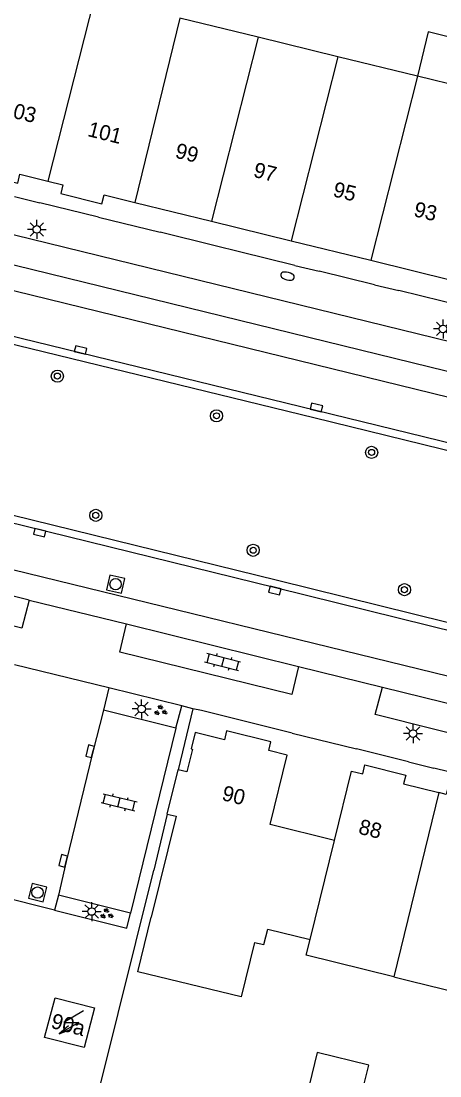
# Model space of a CAD drawing. Extents: x 125000 to 129004, y 397500 to 399008.
# Drawn here: x 126409.3 to 126436.9, y 398309.3 to 398378.8 of the extents above; entities that cross this region are included whole.
import ezdxf

# ---------------------------------------------------------------- set-up
doc = ezdxf.new("R2010")
doc.units = 0
for name, color, linetype in [('gg-afsc-hekwerk', 7, 'Continuous'), ('gg-afsc-muur', 7, 'Continuous'), ('gg-anno-huisnummerreeks BGT', 7, 'Continuous'), ('gg-bbg-gedigitaliseerde bebouwing', 7, 'Continuous'), ('gg-bbg-hoofdgebouw', 7, 'Continuous'), ('gg-bbg-luifel en loopbrug', 7, 'Continuous'), ('gg-bbg-tussenscheiding', 7, 'Continuous'), ('gg-knt-verharding', 7, 'Continuous'), ('gg-knt-verharding nz', 7, 'Continuous'), ('gt-grn-weggrens', 7, 'Continuous'), ('gt-symb-boom', 7, 'Continuous'), ('gt-symb-brandkraan', 7, 'Continuous'), ('gt-symb-groenvak', 7, 'Continuous'), ('gt-symb-klinker verharding', 7, 'Continuous'), ('gt-symb-kolk', 7, 'Continuous'), ('gt-symb-lichtmast', 7, 'Continuous'), ('gt-symb-rioolschacht', 7, 'Continuous'), ('gt-symb-trafo symbool', 7, 'Continuous')]:
    doc.layers.add(name, color=color, linetype=linetype)

# ---------------------------------------------------------------- blocks, each defined once
blk = doc.blocks.new('gt0-LMAST')
at = {"layer": 'gt-symb-lichtmast'}
for p, q in [((-0.182, 0.173), (-0.447, 0.438)), ((-0.005, 0.246), (-0.005, 0.621)), ((0.172, 0.173), (0.437, 0.438)), ((-0.255, -0.004), (-0.63, -0.004)), ((-0.182, -0.181), (-0.447, -0.446)), ((-0.005, -0.254), (-0.005, -0.629)), ((0.437, -0.446), (0.172, -0.181)), ((0.245, -0.004), (0.62, -0.004))]:
    blk.add_line(p, q, dxfattribs=at)
blk.add_circle((-0.005, -0.004), 0.25, dxfattribs=at)
blk = doc.blocks.new('gt0-KOLK')
at = {"layer": 'gt-symb-kolk'}
blk.add_lwpolyline([(0, 0), (0.375, 0), (0.375, 0.4), (-0.375, 0.4), (-0.375, 0), (0, 0)], dxfattribs=at)
blk = doc.blocks.new('gt0-GRVAK')
at = {"layer": 'gt-symb-groenvak'}
for p, q in [((-0.11, 0.189), (-0.228, 0.24)), ((-0.182, 0.153), (0.088, 0.153)), ((-0.091, 0.211), (-0.156, 0.322)), ((-0.047, 0.214), (-0.047, 0.393)), ((-0.004, 0.211), (0.061, 0.322)), ((0.015, 0.189), (0.133, 0.24)), ((0.262, -0.052), (0.197, 0.059)), ((0.305, -0.049), (0.305, 0.13)), ((0.349, -0.052), (0.414, 0.059)), ((-0.245, -0.228), (-0.363, -0.177)), ((-0.318, -0.264), (-0.047, -0.264)), ((-0.226, -0.206), (-0.291, -0.095)), ((-0.183, -0.203), (-0.183, -0.024)), ((-0.139, -0.206), (-0.074, -0.095)), ((-0.12, -0.228), (-0.002, -0.177)), ((0.243, -0.074), (0.125, -0.023)), ((0.17, -0.11), (0.441, -0.11)), ((0.368, -0.074), (0.486, -0.023))]:
    blk.add_line(p, q, dxfattribs=at)
blk = doc.blocks.new('gt0-KL1')
at = {"layer": 'gt-symb-klinker verharding'}
for p, q in [((-1.15, 0.3), (1.15, 0.3)), ((-1, -0.3), (-1, 0.3)), ((-0.5, 0.3), (-0.5, 0.45)), ((0, -0.3), (0, 0.3)), ((0.5, 0.3), (0.5, 0.45)), ((1, -0.3), (1, 0.3)), ((-1.15, -0.3), (1.15, -0.3)), ((-0.5, -0.45), (-0.5, -0.3)), ((0.5, -0.45), (0.5, -0.3))]:
    blk.add_line(p, q, dxfattribs=at)
blk = doc.blocks.new('gt0-RS')
at = {"layer": 'gt-symb-rioolschacht'}
blk.add_lwpolyline([(-0.5, -0.5), (0.5, -0.5), (0.5, 0.5), (-0.5, 0.5)], close=True, dxfattribs=at)
blk.add_circle((0, 0), 0.375, dxfattribs=at)
blk = doc.blocks.new('gt0-HSP')
at = {"layer": 'gt-symb-trafo symbool'}
for points in [[(0.771, 0.746), (-0.529, -0.004), (0.471, -0.004), (-0.829, -0.754)], [(-0.217, -0.24), (-0.829, -0.754), (-0.077, -0.48)]]:
    blk.add_lwpolyline(points, dxfattribs=at)
blk = doc.blocks.new('gt0-BR')
at = {"layer": 'gt-symb-brandkraan'}
for centre, radius, start, end in [((-0.244, 0), 0.206, 107.56694, 252.43307), ((0.599, -2.664), 3, 106.89205, 107.56694), ((0, -0.691), 0.938, 73.10799, 106.89205), ((-0.599, -2.664), 3, 72.43309, 73.10799), ((0.244, 0), 0.206, 287.56695, 72.43309), ((0.599, 2.664), 3, 252.43307, 253.10797), ((0, 0.691), 0.938, 253.10797, 286.89206), ((-0.599, 2.664), 3, 286.89206, 287.56695)]:
    blk.add_arc(centre, radius, start, end, dxfattribs=at)
blk = doc.blocks.new('gt0-BOOM')
at = {"layer": 'gt-symb-boom'}
for radius in [0.4, 0.2]:
    blk.add_circle((0, 0), radius, dxfattribs=at)

msp = doc.modelspace()

# ---------------------------------------------------------------- linework, layer by layer
at = {"layer": 'gg-afsc-hekwerk'}
msp.add_line((126414.543, 398308.615), (126418.065, 398322.828), dxfattribs=at)
at = {"layer": 'gg-afsc-muur'}
for p, q in [((126414.429, 398365.859), (126410.562, 398366.806)), ((126422.12, 398363.973), (126418.482, 398364.873)), ((126427.37, 398362.69), (126423.724, 398363.588)), ((126432.61, 398361.413), (126428.972, 398362.305)), ((126443.124, 398358.85), (126434.215, 398361.037)), ((126427.199, 398331.86), (126421.219, 398333.347)), ((126434.865, 398329.972), (126431.431, 398330.821)), ((126440.386, 398328.611), (126436.524, 398329.564))]:
    msp.add_line(p, q, dxfattribs=at)
at = {"layer": 'gg-bbg-gedigitaliseerde bebouwing'}
msp.add_lwpolyline([(126424.7, 398318.075), (126423.823, 398314.48), (126417.022, 398316.139), (126417.899, 398319.734)], dxfattribs=at)
at = {"layer": 'gg-bbg-hoofdgebouw'}
for p, q in [((126424.952, 398377.721), (126419.787, 398378.984)), ((126430.203, 398376.437), (126424.952, 398377.721)), ((126435.443, 398375.156), (126430.203, 398376.437)), ((126440.76, 398373.855), (126435.443, 398375.156)), ((126416.811, 398366.835), (126421.875, 398365.593)), ((126421.875, 398365.593), (126427.126, 398364.306)), ((126427.126, 398364.306), (126432.365, 398363.022)), ((126432.365, 398363.022), (126437.771, 398361.696)), ((126418.954, 398326.528), (126419.673, 398329.451))]:
    msp.add_line(p, q, dxfattribs=at)
for points in [[(126405.55, 398369.585), (126406.542, 398369.342), (126406.401, 398368.765), (126409.104, 398368.1), (126409.249, 398368.693), (126411.084, 398368.242)], [(126411.084, 398368.242), (126412.078, 398367.997), (126411.935, 398367.414), (126414.647, 398366.747), (126414.79, 398367.33), (126416.811, 398366.835)], [(126429.969, 398324.795), (126425.737, 398325.836), (126426.861, 398330.407), (126425.641, 398330.707), (126425.784, 398331.288), (126422.869, 398332.005), (126422.726, 398331.424), (126420.789, 398331.9), (126420.523, 398330.83), (126420.63, 398330.803), (126420.257, 398329.306), (126419.673, 398329.451)], [(126429.969, 398324.795), (126431.093, 398329.366), (126431.839, 398329.183), (126431.982, 398329.764), (126434.674, 398329.102), (126434.531, 398328.521), (126436.854, 398327.95)], [(126442.396, 398326.616), (126440.051, 398327.192), (126440.194, 398327.775), (126437.487, 398328.412), (126437.349, 398327.828), (126436.854, 398327.95)], [(126418.954, 398326.528), (126419.537, 398326.385), (126417.899, 398319.734)], [(126424.7, 398318.075), (126425.326, 398317.922), (126425.577, 398318.952), (126428.376, 398318.259)], [(126433.884, 398315.803), (126428.122, 398317.23), (126428.376, 398318.259)], [(126433.884, 398315.803), (126434.938, 398315.542), (126439.42, 398314.444)], [(126411.567, 398314.428), (126414.162, 398313.754), (126413.483, 398311.139), (126410.867, 398311.803), (126411.567, 398314.428)]]:
    msp.add_lwpolyline(points, dxfattribs=at)
at = {"layer": 'gg-bbg-luifel en loopbrug'}
for points in [[(126440.76, 398373.855), (126441.473, 398376.769), (126436.156, 398378.07), (126435.443, 398375.156)], [(126431.525, 398307.078), (126432.241, 398309.991), (126428.842, 398310.826), (126428.127, 398307.917)]]:
    msp.add_lwpolyline(points, dxfattribs=at)
at = {"layer": 'gg-bbg-tussenscheiding'}
for p, q in [((126414.158, 398380.361), (126411.084, 398368.242)), ((126419.787, 398378.984), (126416.811, 398366.835)), ((126424.952, 398377.721), (126421.875, 398365.593)), ((126430.203, 398376.437), (126427.126, 398364.306)), ((126435.443, 398375.156), (126432.365, 398363.022)), ((126436.854, 398327.95), (126433.884, 398315.803)), ((126428.376, 398318.259), (126429.969, 398324.795))]:
    msp.add_line(p, q, dxfattribs=at)
at = {"layer": 'gg-knt-verharding'}
for p, q in [((126365.213, 398373.39), (126448.323, 398353.049)), ((126408.89, 398367.225), (126410.562, 398366.806)), ((126414.429, 398365.859), (126418.482, 398364.873)), ((126423.724, 398363.588), (126422.12, 398363.973)), ((126427.37, 398362.69), (126428.972, 398362.305)), ((126432.61, 398361.413), (126434.215, 398361.037)), ((126409.86, 398340.631), (126350.056, 398355.381)), ((126409.86, 398340.631), (126416.28, 398339.055)), ((126416.28, 398339.055), (126427.6, 398336.257)), ((126427.6, 398336.257), (126433.146, 398334.899)), ((126415.105, 398334.846), (126414.758, 398333.386)), ((126419.912, 398333.662), (126415.105, 398334.846)), ((126433.146, 398334.899), (126445.088, 398331.948)), ((126419.527, 398332.2), (126414.758, 398333.386)), ((126419.527, 398332.2), (126419.912, 398333.662)), ((126420.653, 398333.472), (126419.673, 398329.451)), ((126421.219, 398333.347), (126420.653, 398333.472)), ((126419.527, 398332.2), (126416.538, 398319.993)), ((126427.199, 398331.86), (126431.431, 398330.821)), ((126434.865, 398329.972), (126436.524, 398329.564)), ((126418.954, 398326.528), (126418.065, 398322.828)), ((126411.793, 398321.176), (126411.531, 398320.194)), ((126416.538, 398319.993), (126411.793, 398321.176))]:
    msp.add_line(p, q, dxfattribs=at)
for points in [[(126448.323, 398353.049), (126448.796, 398354.91), (126365.644, 398375.274), (126365.213, 398373.39)], [(126449.021, 398347.643), (126428.625, 398352.641), (126397.504, 398360.23), (126353.639, 398370.97)], [(126449.141, 398348.128), (126428.744, 398353.127), (126397.623, 398360.716), (126363.062, 398369.176)], [(126350.892, 398360.466), (126426.213, 398341.94), (126446.374, 398336.947)], [(126350.765, 398359.982), (126426.093, 398341.455), (126446.254, 398336.462)], [(126409.86, 398340.631), (126409.361, 398338.78), (126349.566, 398353.538), (126350.056, 398355.381)], [(126427.6, 398336.257), (126427.167, 398334.401), (126415.827, 398337.205), (126416.28, 398339.055)], [(126445.088, 398331.948), (126444.643, 398330.084), (126432.666, 398333.08), (126433.146, 398334.899)], [(126414.758, 398333.386), (126414.06, 398330.619), (126412.286, 398323.397), (126411.793, 398321.176)], [(126411.531, 398320.194), (126416.287, 398319.015), (126416.538, 398319.993)]]:
    msp.add_lwpolyline(points, dxfattribs=at)
at = {"layer": 'gg-knt-verharding nz'}
msp.add_line((126504.991, 398319.074), (126347.368, 398357.642), dxfattribs=at)
msp.add_lwpolyline([(126539.849, 398328.941), (126484.861, 398342.384), (126363.791, 398372.034)], dxfattribs=at)
at = {"layer": 'gt-grn-weggrens'}
for p, q in [((126415.105, 398334.846), (126408.897, 398336.37)), ((126420.653, 398333.472), (126419.912, 398333.662)), ((126411.531, 398320.194), (126405.31, 398321.765))]:
    msp.add_line(p, q, dxfattribs=at)

# ---------------------------------------------------------------- block references
at = {"layer": 'gt-symb-boom'}
for p in [(126411.714, 398355.39), (126422.204, 398352.775), (126432.425, 398350.364), (126414.243, 398346.215), (126424.621, 398343.912), (126434.588, 398341.316)]:
    msp.add_blockref('gt0-BOOM', p, dxfattribs=at)
at = {"layer": 'gt-symb-brandkraan', "rotation": 166.28353067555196}
msp.add_blockref('gt0-BR', (126426.886, 398361.982), dxfattribs=at)
at = {"layer": 'gt-symb-groenvak'}
for p, rotation in [((126418.499, 398333.34), -13.660766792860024), ((126414.949, 398319.931), -13.647238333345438)]:
    msp.add_blockref('gt0-GRVAK', p, dxfattribs=dict(at, rotation=rotation))
at = {"layer": 'gt-symb-klinker verharding'}
for p, rotation in [((126422.604, 398336.542), 165.51896562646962), ((126415.78, 398327.305), -13.647238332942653)]:
    msp.add_blockref('gt0-KL1', p, dxfattribs=dict(at, rotation=rotation))
at = {"layer": 'gt-symb-kolk'}
for p, rotation in [((126413.193, 398356.915), -13.71646932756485), ((126428.744, 398353.127), -13.702889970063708), ((126410.594, 398345.268), 166.17220496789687), ((126426.093, 398341.455), 166.17220496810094), ((126414.06, 398330.619), 75.82485794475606), ((126412.286, 398323.397), 76.17220496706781)]:
    msp.add_blockref('gt0-KOLK', p, dxfattribs=dict(at, rotation=rotation))
at = {"layer": 'gt-symb-lichtmast'}
for p in [(126410.364, 398365.06), (126437.139, 398358.505), (126417.271, 398333.457), (126435.16, 398331.835), (126413.981, 398320.11)]:
    msp.add_blockref('gt0-LMAST', p, dxfattribs=at)
at = {"layer": 'gt-symb-rioolschacht'}
for p, rotation in [((126415.554, 398341.675), -102.82712342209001), ((126410.406, 398321.352), 76.06098564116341)]:
    msp.add_blockref('gt0-RS', p, dxfattribs=dict(at, rotation=rotation))
at = {"layer": 'gt-symb-trafo symbool'}
msp.add_blockref('gt0-HSP', (126412.665, 398312.806), dxfattribs=at)

# ---------------------------------------------------------------- texts
at = {"layer": 'gg-anno-huisnummerreeks BGT'}
for s, rotation, p in [('103', 346.4, (126408.009, 398372.589)), ('101', 346.2, (126413.651, 398371.215)), ('99', 346.2, (126419.419, 398369.798)), ('97', 346.2, (126424.577, 398368.534)), ('95', 346.2, (126429.822, 398367.248)), ('93', 346.2, (126435.145, 398365.943)), ('90', 346.2, (126422.501, 398327.46)), ('88', 346.2, (126431.503, 398325.246)), ('90a', 345.4, (126411.233, 398312.449))]:
    msp.add_text(s, height=1, rotation=rotation, dxfattribs=at).set_placement(p)

doc.saveas('drawing.dxf')
